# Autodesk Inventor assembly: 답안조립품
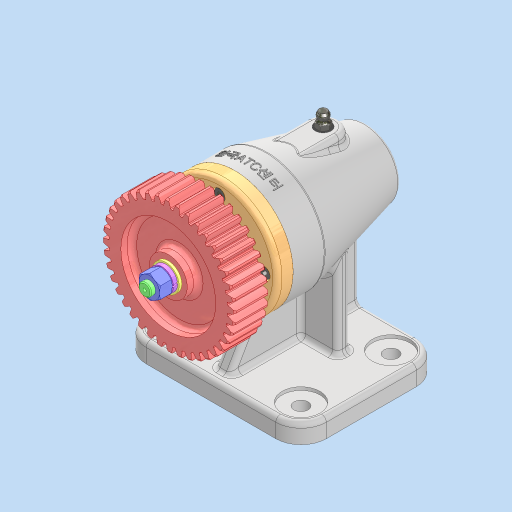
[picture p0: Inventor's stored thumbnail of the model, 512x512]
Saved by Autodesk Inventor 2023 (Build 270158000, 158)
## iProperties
Created: 2024-12
Part Number: 답안조립품
Document SubType Name: Assembly
Designer: asung
Author: asung
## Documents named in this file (15)
- C:\Users\asung\Desktop\741204V1010\답안조립품.iam
- C:\Users\asung\Desktop\741204V1010\본체.ipt
- C:\Users\asung\Desktop\741204V1010\앵귤러 볼 제어링 7204A.ipt
- C:\Users\asung\Desktop\741204V1010\커버.ipt
- C:\Users\asung\Desktop\741204V1010\오일 실 20 32 8.ipt
- C:\Users\asung\Desktop\741204V1010\축.ipt
- C:\Users\asung\Desktop\741204V1010\평행 키 4x4x14.ipt
- C:\Users\asung\Desktop\741204V1010\스퍼기어.ipt
- C:\Users\asung\Desktop\741204V1010\스프링 와셔 M8.ipt
- C:\Users\asung\Desktop\741204V1010\육각 너트 M8.ipt
- C:\Users\asung\Desktop\741204V1010\평와셔 M8.ipt
- C:\Users\asung\Desktop\741204V1010\앵귤러 볼 베어링 7003A.ipt
- C:\Users\asung\Desktop\741204V1010\그리스 니플 M6x0.75.ipt
- C:\Users\asung\Desktop\741204V1010\실링.ipt
- C:\Users\asung\Desktop\741204V1010\육각 소켓 머리 볼트 M4x10.ipt
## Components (1 placed, 1 different names)
1. 그리스 니플 M6x0.75:1
